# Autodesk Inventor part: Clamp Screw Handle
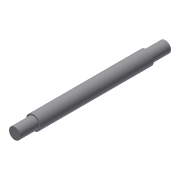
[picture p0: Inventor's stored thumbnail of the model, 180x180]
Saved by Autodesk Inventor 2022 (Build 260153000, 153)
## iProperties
Created: 2002-02
Part Number: Clamp Screw Handle
Document SubType Name: Modeling
Designer: ***
Density: 1 g/cm^3
Material: Generic
Appearance: Default
Control State: 0
Master: False
Checked Out: False
Shininess: 77.0
Length Units: 11269
Angle Units: 11279
Time Units: 11290
Mass Units: 11283
Length Display Precision: 3
Angle Display Precision: 2
Compacted: True
Density: 0.0
Volumn: 0.0
Area: 0.0
PropertySet Name: Model Information
Author: ***
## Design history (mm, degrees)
sketch "Sketch1"
  geometry: L1 (0, 105)-(4, 105); L2 (4, 105)-(4, 92); L3 (4, 92)-(5, 92); L4 (5, 92)-(5, 13); L5 (5, 13)-(4, 13); L6 (4, 13)-(4, 0); L7 (4, 0)-(0, 0); L8 (0, 0)-(0, 105)
  constraints: 16 end point, 5 parallel, 2 equal length, 1 collinear, 1 horizontal, 1 perpendicular
  dimensions: "d0" = 10 diameter of L4 L8; "d1" = 8 diameter of L2 L8; "d2" = 13 distance of L1.end L2.end; "d3" = 79 distance of L3.end L4.end
revolve "Revolution1" sketch "Sketch1" stored, may be unused: angle "d4" = 90 deg
body "Solid1"
